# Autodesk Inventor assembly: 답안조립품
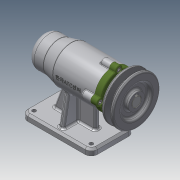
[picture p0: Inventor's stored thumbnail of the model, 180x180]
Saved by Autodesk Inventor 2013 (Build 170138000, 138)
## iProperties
Created: 2019-07
Part Number: 답안조립품
Document SubType Name: Assembly
Designer: user
Author: user
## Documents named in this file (12)
- C:\Users\user\Desktop\490704V1083\답안조립품.iam
- C:\Users\user\Desktop\490704V1083\본체.ipt
- C:\Users\user\Desktop\490704V1083\V벨트풀리.ipt
- C:\Users\user\Desktop\490704V1083\멈춤나사 M3.ipt
- C:\Users\user\Desktop\490704V1083\베어링 6004.ipt
- C:\Users\user\Desktop\490704V1083\베어링 51202.ipt
- C:\Users\user\Desktop\490704V1083\볼트 M4.ipt
- C:\Users\user\Desktop\490704V1083\어댑터슬리브.ipt
- C:\Users\user\Desktop\490704V1083\오일 실.ipt
- C:\Users\user\Desktop\490704V1083\축.ipt
- C:\Users\user\Desktop\490704V1083\커버.ipt
- C:\Users\user\Desktop\490704V1083\키 5 x 5 x 16.ipt
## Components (1 placed, 1 different names)
1. V벨트풀리:1
